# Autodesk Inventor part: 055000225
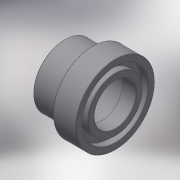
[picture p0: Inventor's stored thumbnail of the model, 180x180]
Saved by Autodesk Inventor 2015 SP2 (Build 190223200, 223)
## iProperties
Created: 2017-10
Part Number: 055000225
Material: Generic
Description: PLASSON FLANGE AD.+O-RING-CE 225
Document SubType Name: Modeling
Designer: KIM
Density: 1 g/cm^3
Appearance: Default
Author: KIM
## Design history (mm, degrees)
derived "055000.ipt"
feature "Solid1::055000.ipt"
tag "TaggingFeature1"
body "Solid1"
other parameters: "d0" = 133, "d1" = 249, "d2" = 225, "d3" = 202.5, "d4" = 25, "d5" = 119, "d6" = 272, "d8" = 7.5, "d11" = 2.25, "d12" = 7.5, "d15" = 10.425, "d_" = 225, "E_" = 249, "E_1" = 272, "l_" = 119, "B_" = 25, "H_" = 133, "d14" = 34.75
